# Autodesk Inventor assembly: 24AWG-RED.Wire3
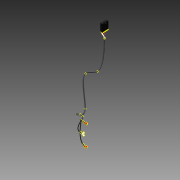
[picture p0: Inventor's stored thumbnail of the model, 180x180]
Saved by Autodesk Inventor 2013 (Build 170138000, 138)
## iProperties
ParentFileIdentifier: 5|1|0|0|176|2|0|0|80|0|65|0|84|0|72|0|83|0|59|0|67|0|58|0|92|0|80|0|114|0|111|0|103|0|114|0|97|0|109|0|32|0|70|0|105|0|108|0|101|0|115|0|92|0|65|0|117|0|116|0|1
Part Number: 24AWG-RED.Wire3
Material: Default
Description: 24AWG-RED
Density: 1 g/cm^3
Part Number: 24AWG-WHT.Wire1
Description: 24AWG-WHT
Part Number: 24AWG-WHT.Wire2
Part Number: 24AWG-RED.Wire5
Part Number: 24AWG-BLK.Wire4
Description: 24AWG-BLK
Part Number: 24AWG-BLK.Wire6
Created: 2007-02
Part Number: Front Panel Harness
Document SubType Name: Assembly
Designer: floress
Mass: 0.35267 g
Surface Area: 21.3815 cm^2
Volume: 0.35267 cm^3
HarnessSettings: <HarnessSettings><Defaults><Segments><Diameter value="0.200 in" fromwires="True"/><Offset value="0.100 in"/><ColorStyle value="Blue"/><RoundUp value=""/><BendRa
CableDummyParamRefKey: Key:16|2|0|0|16|0|0|0|237|1|0|0|0|0|0|0|129|0|0|0|0|0|0|0|Level:1
Author: floress
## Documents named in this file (3)
- Z:\_DATEN\Personal Computer\Aip\Front Panel Harness.iam
- Z:\_DATEN\Personal Computer\Aip\Front Panel Harness.ipt
- Z:\_DATEN\Personal Computer\Aip\Front Panel Connector.ipt
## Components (8 placed, 8 different names)
1. Front Panel Connector:1
2. Front Panel Harness
3. HA_VC_137:1
4. HA_VC_140:1
5. HA_VC_143:1
6. HA_VC_146:1
7. HA_VC_149:1
8. HA_VC_152:1
